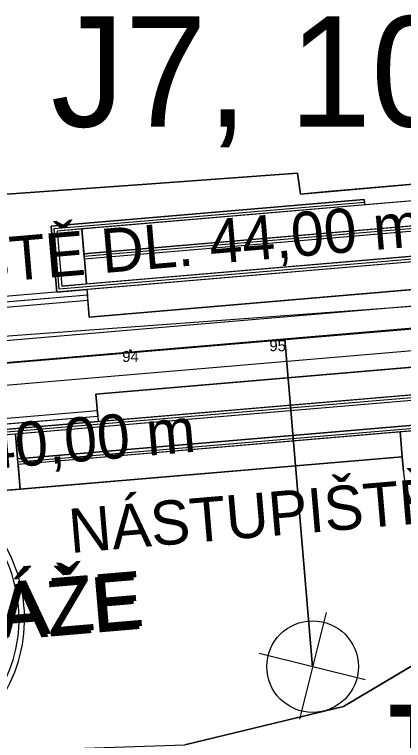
# Model space of a CAD drawing. Extents: x -606444 to -604546, y -1158114 to -1156869.
# Drawn here: x -605528.3 to -605493.1, y -1157172.8 to -1157107.1 of the extents above; entities that cross this region are included whole.
import ezdxf

# ---------------------------------------------------------------- set-up
doc = ezdxf.new("R2010")
doc.units = 0
for name, color, linetype in [('ARCHIVNÍ SONDY', 7, 'Continuous'), ('B_CHOD', 7, 'Continuous'), ('B_TRAM', 7, 'Continuous'), ('B_ZELEN', 7, 'Continuous'), ('geofyzikální profily_předběžný GTP', 7, 'Continuous'), ('jádrové vrty_předběžný GTP', 7, 'Continuous'), ('netisk', 7, 'Continuous'), ('netisk2', 7, 'Continuous'), ('NS_VB', 7, 'Continuous'), ('NS_VB_OBJ', 7, 'Continuous'), ('NS_VB_POP', 7, 'Continuous'), ('NS_VB_POPIS', 7, 'Continuous'), ('OSA', 7, 'Continuous'), ('podélný profil trasou tramvaje', 7, 'Continuous'), ('sondy předběžného průzkumu', 7, 'Continuous')]:
    doc.layers.add(name, color=color, linetype=linetype)

# ---------------------------------------------------------------- blocks, each defined once
blk = doc.blocks.new('IG vrt archivní')
at = {"layer": 'sondy předběžného průzkumu'}
for p, q in [((0.406, 1.636), (-0.393, -1.584)), ((1.589, -0.397), (-1.612, 0.402))]:
    blk.add_line(p, q, dxfattribs=at)
blk.add_circle((0.001, 0.002), 1.382, dxfattribs=at)

msp = doc.modelspace()

# ---------------------------------------------------------------- linework, layer by layer
for p, q in [((-605504.54, -1157136.55), (-605504.64, -1157136.45)), ((-605504.54, -1157136.55), (-605504.64, -1157136.65)), ((-605504.54, -1157136.55), (-605504.44, -1157136.45)), ((-605504.54, -1157136.55), (-605504.44, -1157136.65)), ((-605517.86, -1157137.52), (-605517.96, -1157137.42)), ((-605517.86, -1157137.52), (-605517.76, -1157137.42)), ((-605517.86, -1157137.52), (-605517.96, -1157137.62)), ((-605517.86, -1157137.52), (-605517.76, -1157137.62))]:
    msp.add_line(p, q)
at = {"layer": 'B_CHOD'}
for points in [[(-605487.683, -1157123.541), (-605522.258, -1157126.481), (-605522.068, -1157128.723), (-605487.492, -1157125.783), (-605487.683, -1157123.541)], [(-605477.908, -1157128.731), (-605477.993, -1157127.735), (-605478.184, -1157125.493), (-605481.173, -1157125.747), (-605480.982, -1157127.989), (-605480.94, -1157128.487), (-605521.792, -1157131.962), (-605521.58, -1157134.453), (-605477.739, -1157130.724), (-605477.908, -1157128.731)], [(-605521.835, -1157131.463), (-605480.982, -1157127.989), (-605481.173, -1157125.747), (-605522.025, -1157129.221), (-605521.835, -1157131.463)], [(-605524.077, -1157131.654), (-605521.835, -1157131.463), (-605522.025, -1157129.221), (-605522.068, -1157128.723), (-605522.258, -1157126.481), (-605524.5, -1157126.672), (-605524.077, -1157131.654)], [(-605487.446, -1157141.084), (-605487.403, -1157141.582), (-605487.213, -1157143.824), (-605484.223, -1157143.57), (-605484.414, -1157141.328), (-605484.456, -1157140.829), (-605476.934, -1157140.19), (-605477.145, -1157137.699), (-605520.987, -1157141.427), (-605520.818, -1157143.42), (-605520.775, -1157143.918), (-605487.446, -1157141.084)], [(-605487.403, -1157141.582), (-605528.256, -1157145.056), (-605528.065, -1157147.298), (-605487.213, -1157143.824), (-605487.403, -1157141.582)], [(-605490.153, -1157148.189), (-605490.268, -1157146.844), (-605490.458, -1157144.602), (-605493.448, -1157144.856), (-605493.257, -1157147.098), (-605493.142, -1157148.443)], [(-605530.074, -1157150.229), (-605527.832, -1157150.038), (-605528.023, -1157147.796), (-605528.065, -1157147.298), (-605528.256, -1157145.056), (-605530.498, -1157145.247), (-605530.074, -1157150.229)], [(-605527.832, -1157150.038), (-605493.257, -1157147.098), (-605493.448, -1157144.856), (-605528.023, -1157147.796), (-605527.832, -1157150.038)]]:
    msp.add_lwpolyline(points, dxfattribs=at)
msp.add_arc((-605485.171, -1157147.765), 8, 184.8613, 229.7761, dxfattribs=at)
at = {"layer": 'B_TRAM'}
for p, q in [((-605477.739, -1157130.724), (-605521.58, -1157134.453)), ((-605521.75, -1157132.46), (-605584.76, -1157137.819)), ((-605521.58, -1157134.453), (-605521.75, -1157132.46)), ((-605520.987, -1157141.427), (-605477.145, -1157137.699)), ((-605520.818, -1157143.42), (-605520.987, -1157141.427)), ((-605583.832, -1157148.78), (-605520.818, -1157143.42))]:
    msp.add_line(p, q, dxfattribs=at)
at = {"layer": 'B_ZELEN'}
for p, q in [((-605516.38, -1157122.43), (-605502.73, -1157121.42)), ((-605502.73, -1157121.42), (-605502.45, -1157123.32)), ((-605502.45, -1157123.32), (-605487.81, -1157122.046)), ((-605542.57, -1157124.27), (-605516.38, -1157122.43)), ((-605487.683, -1157123.541), (-605496.651, -1157124.303)), ((-605496.693, -1157123.805), (-605525.041, -1157126.216)), ((-605496.651, -1157124.303), (-605496.693, -1157123.805)), ((-605525.041, -1157126.216), (-605524.532, -1157132.195)), ((-605524.532, -1157132.195), (-605521.792, -1157131.962)), ((-605521.792, -1157131.962), (-605521.75, -1157132.46)), ((-605521.75, -1157132.46), (-605600.807, -1157139.3)), ((-605583.832, -1157148.78), (-605520.818, -1157143.42)), ((-605520.775, -1157143.918), (-605530.54, -1157144.749)), ((-605520.818, -1157143.42), (-605520.775, -1157143.918))]:
    msp.add_line(p, q, dxfattribs=at)
for points in [[(-605493.142, -1157148.443), (-605493.257, -1157147.098), (-605530.074, -1157150.229), (-605530.294, -1157147.647), (-605593.013, -1157177.89)], [(-605595.569, -1157184.021), (-605592.294, -1157180.09), (-605579.33, -1157177.48), (-605552.67, -1157174.72), (-605533.88, -1157173.88), (-605512.92, -1157173.16), (-605498.57, -1157169.69), (-605484.706, -1157161.461)]]:
    msp.add_lwpolyline(points, dxfattribs=at)
msp.add_arc((-605485.171, -1157147.765), 8, 184.8613, 229.7761, dxfattribs=at)
at = {"layer": 'geofyzikální profily_předběžný GTP'}
msp.add_lwpolyline([(-605670.777, -1157141.05), (-605656.017, -1157139.471), (-605613.877, -1157139.359), (-605584.802, -1157137.32), (-605531.406, -1157136.329), (-605491.561, -1157133.405), (-605482.073, -1157135.613), (-605438.781, -1157126.664), (-605383.232, -1157124.522), (-605352.341, -1157123.33), (-605321.946, -1157125.999), (-605284.139, -1157130.42), (-605243.303, -1157142.595), (-605207.83, -1157158.833), (-605179.979, -1157186.151), (-605165.292, -1157202.666), (-605149.231, -1157223.341), (-605135.067, -1157244.471), (-605115.915, -1157286.275), (-605103.218, -1157315.843), (-605095.331, -1157330.321), (-605036.966, -1157403.361), (-604999.079, -1157442.536), (-604970.798, -1157468.352)], dxfattribs=at)
at = {"layer": 'netisk'}
msp.add_line((-605503.891, -1157136.461), (-605501.37, -1157166.102), dxfattribs=at)
at = {"layer": 'netisk2'}
msp.add_line((-605501.37, -1157166.102), (-605503.891, -1157136.461), dxfattribs=at)
at = {"layer": 'NS_VB'}
for p, q in [((-605470.073, -1157120.538), (-605499.97, -1157123.08)), ((-605502.73, -1157121.42), (-605516.38, -1157122.43)), ((-605502.45, -1157123.32), (-605502.73, -1157121.42)), ((-605516.38, -1157122.43), (-605542.57, -1157124.27)), ((-605487.683, -1157123.541), (-605524.5, -1157126.672)), ((-605499.97, -1157123.08), (-605502.45, -1157123.32)), ((-605525.041, -1157126.216), (-605496.693, -1157123.805)), ((-605496.693, -1157123.805), (-605496.651, -1157124.303)), ((-605524.532, -1157132.195), (-605525.041, -1157126.216)), ((-605524.5, -1157126.672), (-605524.077, -1157131.654)), ((-605522.258, -1157126.481), (-605521.835, -1157131.463)), ((-605480.94, -1157128.487), (-605524.532, -1157132.195)), ((-605521.792, -1157131.962), (-605521.58, -1157134.453)), ((-605487.446, -1157141.084), (-605530.54, -1157144.749)), ((-605520.987, -1157141.427), (-605520.775, -1157143.918)), ((-605527.832, -1157150.038), (-605528.256, -1157145.056)), ((-605493.142, -1157148.443), (-605493.448, -1157144.856)), ((-605493.257, -1157147.098), (-605530.074, -1157150.229)), ((-605484.706, -1157161.461), (-605498.57, -1157169.69)), ((-605498.57, -1157169.69), (-605512.92, -1157173.16))]:
    msp.add_line(p, q, dxfattribs=at)
for points in [[(-605473.443, -1157124.588), (-605522.068, -1157128.723)], [(-605473.401, -1157125.086), (-605522.025, -1157129.221)], [(-605480.982, -1157127.989), (-605524.077, -1157131.654)], [(-605477.739, -1157130.724), (-605521.58, -1157134.453)], [(-605521.75, -1157132.46), (-605584.76, -1157137.819)], [(-605477.145, -1157137.699), (-605520.987, -1157141.427)], [(-605487.403, -1157141.582), (-605530.498, -1157145.247)], [(-605479.441, -1157143.163), (-605528.065, -1157147.298)], [(-605583.832, -1157148.78), (-605520.818, -1157143.42)], [(-605479.398, -1157143.661), (-605528.023, -1157147.796)]]:
    msp.add_lwpolyline(points, dxfattribs=at)
for centre, radius, start, end in [((-605540.939, -1157161.779), 13.5, 274.8613, 120.82453), ((-605485.171, -1157147.765), 8, 184.8613, 229.7761)]:
    msp.add_arc(centre, radius, start, end, dxfattribs=at)
at = {"layer": 'NS_VB_OBJ'}
for points in [[(-605480.961, -1157128.238), (-605524.304, -1157131.924), (-605524.771, -1157126.444), (-605496.672, -1157124.054)], [(-605473.422, -1157124.837), (-605522.046, -1157128.972)], [(-605521.792, -1157131.962), (-605584.802, -1157137.32)], [(-605521.707, -1157132.958), (-605584.717, -1157138.317)], [(-605487.424, -1157141.333), (-605530.519, -1157144.998)], [(-605583.874, -1157148.281), (-605520.86, -1157142.922)], [(-605560.432, -1157147.291), (-605520.775, -1157143.918)], [(-605528.044, -1157147.547), (-605479.419, -1157143.412)]]:
    msp.add_lwpolyline(points, dxfattribs=at)
msp.add_arc((-605540.939, -1157161.779), 13, 274.8613, 120.82453, dxfattribs=at)
at = {"layer": 'OSA'}
msp.add_line((-605374.147, -1157125.426), (-605584.296, -1157143.299), dxfattribs=at)
for points in [[(-605374.317, -1157123.433), (-605584.465, -1157141.306)], [(-605584.127, -1157145.292), (-605373.977, -1157127.419)]]:
    msp.add_lwpolyline(points, dxfattribs=at)
at = {"layer": 'podélný profil trasou tramvaje'}
msp.add_lwpolyline([(-605358.234, -1157124.224), (-605590.305, -1157143.817), (-605624.537, -1157148.594), (-605648.212, -1157155.583), (-605668.251, -1157164.472)], dxfattribs=at)

# ---------------------------------------------------------------- block references
at = {"layer": 'ARCHIVNÍ SONDY', "xscale": 3, "yscale": 3}
msp.add_blockref('IG vrt archivní', (-605501.37, -1157166.102), dxfattribs=at)

# ---------------------------------------------------------------- texts
for s, p in [('95', (-605505.276, -1157137.55)), ('94', (-605518.596, -1157138.52))]:
    msp.add_text(s, height=1).set_placement(p)
at = {"layer": 'ARCHIVNÍ SONDY'}
msp.add_text('J841', height=10, dxfattribs=at).set_placement((-605497.004, -1157179.524))
at = {"layer": 'jádrové vrty_předběžný GTP'}
msp.add_text('J7, 10m', height=10, dxfattribs=at).set_placement((-605525.056, -1157117.222))
at = {"layer": 'NS_VB_POP'}
for s, p in [('NÁSTUPIŠTĚ DL. 44,00 m', (-605555.286, -1157133.455)), ('OPĚRNÁ ZEĎ DL. 40,00 m', (-605576.999, -1157152.175)), ('NÁSTUPIŠTĚ DL. 44,00 m', (-605523.276, -1157155.823))]:
    msp.add_text(s, height=4, rotation=4.8613, dxfattribs=at).set_placement(p)
at = {"layer": 'NS_VB_POPIS'}
for p in [(-605634.233, -1157172.402), (-605634.461, -1157172.673)]:
    msp.add_text('REZERVA PRO HROMADNÉ GARÁŽE', height=5, rotation=4.8613, dxfattribs=at).set_placement(p)

doc.saveas('drawing.dxf')
